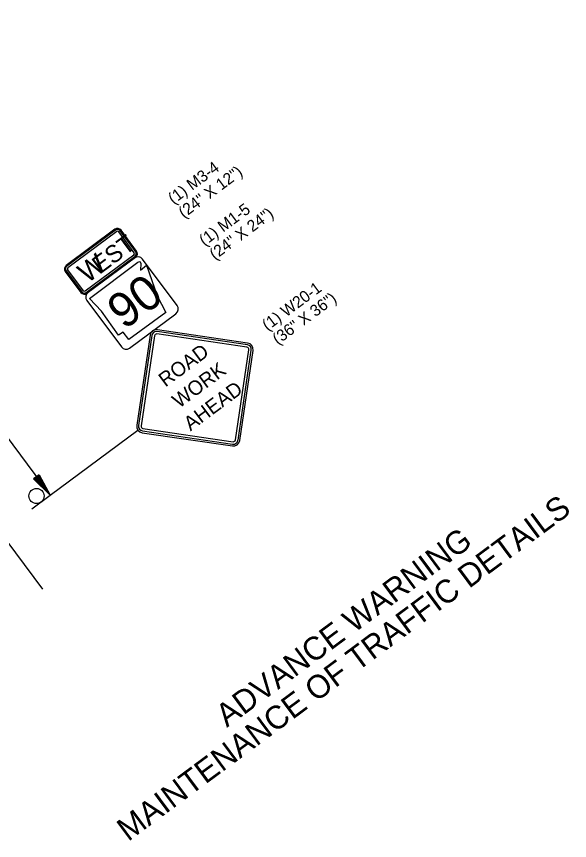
# Model space of a CAD drawing. Extents: x 998982 to 1000630, y 1875366 to 1876934.
# Drawn here: x 1000343 to 1000629.9, y 1875977.1 to 1876404.6 of the extents above; entities that cross this region are included whole.
import ezdxf

# ---------------------------------------------------------------- set-up
doc = ezdxf.new("R2010")
doc.units = 0
for name, color, linetype in [('P_TC_Signs_Permanent', 7, 'Continuous'), ('P_TC_Signs_Temporary', 7, 'Continuous'), ('R_Border Prem', 7, 'Continuous'), ('R_Draft', 7, 'Continuous'), ('STAMP', 7, 'Continuous')]:
    doc.layers.add(name, color=color, linetype=linetype)

msp = doc.modelspace()

# ---------------------------------------------------------------- linework, layer by layer
at = {"layer": 'P_TC_Signs_Permanent'}
for p, q in [((1000394.11, 1876294.21), (1000368.82, 1876275.43)), ((1000394.44, 1876293.76), (1000369.15, 1876274.98)), ((1000395, 1876293), (1000369.71, 1876274.23)), ((1000404.1, 1876282.01), (1000396.05, 1876292.85)), ((1000404.85, 1876282.57), (1000396.8, 1876293.41)), ((1000405.3, 1876282.91), (1000397.26, 1876293.74)), ((1000378.65, 1876262.18), (1000403.94, 1876280.96)), ((1000379.21, 1876261.43), (1000404.5, 1876280.21)), ((1000379.55, 1876260.98), (1000404.84, 1876279.76)), ((1000404.24, 1876279.31), (1000380.15, 1876261.43)), ((1000426.32, 1876254.6), (1000408.43, 1876278.69)), ((1000368.35, 1876272.28), (1000376.4, 1876261.44)), ((1000368.8, 1876272.62), (1000376.85, 1876261.78)), ((1000369.56, 1876273.18), (1000377.61, 1876262.34)), ((1000379.53, 1876257.23), (1000397.42, 1876233.14)), ((1000401.61, 1876232.52), (1000425.7, 1876250.41))]:
    msp.add_line(p, q, dxfattribs=at)
msp.add_lwpolyline([(1000406.76, 1876277.56), (1000407.25, 1876277.23), (1000407.6, 1876276.4), (1000407.39, 1876273.03), (1000410.54, 1876275.55), (1000415.92, 1876259.73), (1000420.57, 1876251.1), (1000401.38, 1876236.97), (1000398.39, 1876240.88), (1000395.88, 1876239.18), (1000387.17, 1876251.65), (1000380.86, 1876258.31), (1000405.98, 1876277.09), (1000406.76, 1876277.56)], dxfattribs=at)
for centre, radius, start, end in [((1000395.45, 1876292.4), 2.25, 36.5953, 126.5953), ((1000395.45, 1876292.4), 1.69, 36.5953, 126.5953), ((1000395.45, 1876292.4), 0.75, 36.5953, 126.5953), ((1000403.5, 1876281.56), 0.75, 306.5953, 36.5953), ((1000406.03, 1876276.9), 3, 36.5953, 126.5953), ((1000403.5, 1876281.56), 1.69, 306.5953, 36.5953), ((1000403.5, 1876281.56), 2.25, 306.5953, 36.5953), ((1000370.16, 1876273.62), 2.25, 126.5953, 216.5953), ((1000370.16, 1876273.62), 1.69, 126.5953, 216.5953), ((1000370.16, 1876273.62), 0.75, 126.5953, 216.5953), ((1000378.21, 1876262.79), 2.25, 216.5953, 306.5953), ((1000378.21, 1876262.79), 1.69, 216.5953, 306.5953), ((1000378.21, 1876262.79), 0.75, 216.5953, 306.5953), ((1000381.94, 1876259.02), 3, 126.5953, 216.5953), ((1000423.91, 1876252.82), 3, 306.5953, 36.5953), ((1000399.82, 1876234.93), 3, 216.5953, 306.5953)]:
    msp.add_arc(centre, radius, start, end, dxfattribs=at)
at = {"layer": 'P_TC_Signs_Temporary'}
for p, q in [((1000462.77, 1876234.26), (1000416.02, 1876241.17)), ((1000462.9, 1876235.19), (1000416.16, 1876242.09)), ((1000412.33, 1876239.25), (1000405.42, 1876192.51)), ((1000413.26, 1876239.11), (1000406.35, 1876192.37)), ((1000414.55, 1876238.92), (1000407.65, 1876192.18)), ((1000462.57, 1876232.96), (1000415.83, 1876239.87)), ((1000456.62, 1876184.94), (1000463.52, 1876231.68)), ((1000457.92, 1876184.75), (1000464.82, 1876231.49)), ((1000458.84, 1876184.61), (1000465.75, 1876231.36)), ((1000408.6, 1876190.9), (1000455.34, 1876183.99)), ((1000408.27, 1876188.67), (1000455.01, 1876181.77)), ((1000408.41, 1876189.6), (1000455.15, 1876182.7))]:
    msp.add_line(p, q, dxfattribs=at)
for centre, radius, start, end in [((1000415.67, 1876238.76), 3.38, 81.5953, 171.5953), ((1000415.67, 1876238.76), 2.44, 81.5953, 171.5953), ((1000415.67, 1876238.76), 1.13, 81.5953, 171.5953), ((1000462.41, 1876231.85), 1.12, 351.5953, 81.5953), ((1000462.41, 1876231.85), 2.44, 351.5953, 81.5953), ((1000462.41, 1876231.85), 3.38, 351.5953, 81.5953), ((1000408.76, 1876192.01), 3.38, 171.5953, 261.5953), ((1000408.76, 1876192.01), 2.44, 171.5953, 261.5953), ((1000408.76, 1876192.01), 1.12, 171.5953, 261.5953), ((1000455.5, 1876185.11), 3.38, 261.5953, 351.5953), ((1000455.5, 1876185.11), 2.44, 261.5953, 351.5953), ((1000455.5, 1876185.11), 1.13, 261.5953, 351.5953)]:
    msp.add_arc(centre, radius, start, end, dxfattribs=at)
at = {"layer": 'R_Draft'}
for p, q in [((1000356.62, 1876107.48), (1000045.75, 1876526.13)), ((1000241.26, 1876316.75), (1000360.5, 1876156.17)), ((1000360.5, 1876156.17), (1000406.05, 1876190)), ((1000354.8, 1876166.85), (1000351.92, 1876164.71)), ((1000351.92, 1876164.71), (1000360.5, 1876156.17)), ((1000352.16, 1876164.89), (1000359.3, 1876157.78)), ((1000352.4, 1876165.07), (1000358.08, 1876159.43)), ((1000352.64, 1876165.25), (1000356.89, 1876161.03)), ((1000352.89, 1876165.44), (1000355.68, 1876162.66)), ((1000353.14, 1876165.62), (1000354.49, 1876164.27)), ((1000353.59, 1876165.95), (1000354.49, 1876164.27)), ((1000353.83, 1876166.13), (1000355.68, 1876162.66)), ((1000354.08, 1876166.32), (1000356.89, 1876161.03)), ((1000354.32, 1876166.49), (1000358.08, 1876159.43)), ((1000354.56, 1876166.68), (1000359.3, 1876157.78)), ((1000354.8, 1876166.85), (1000360.5, 1876156.17))]:
    msp.add_line(p, q, dxfattribs=at)
at = {"layer": 'STAMP'}
msp.add_line((1000351.06, 1876149.17), (1000360.49, 1876156.18), dxfattribs=at)
msp.add_circle((1000353.44, 1876155.82), 3.92, dxfattribs=at)

# ---------------------------------------------------------------- texts
at = {"layer": 'P_TC_Signs_Permanent'}
for s, height, p in [('EST', 9, (1000386.5, 1876270.81)), ('W', 10.5, (1000379.85, 1876265.87)), ('90', 18, (1000398.9, 1876241.71))]:
    msp.add_text(s, height=height, rotation=36.5953, dxfattribs=at).set_placement(p)
at = {"layer": 'P_TC_Signs_Temporary'}
for s, p in [(' ROAD ', (1000418.03, 1876210.37)), ('WORK', (1000427.36, 1876201.08)), ('AHEAD', (1000433.29, 1876189.26))]:
    msp.add_text(s, height=7.5, rotation=36.5953, dxfattribs=at).set_placement(p)
at = {"layer": 'R_Border Prem'}
for s, height, p in [('(1) M3-4', 6, (1000424.43, 1876306.94)), ('(24" X 12")', 6, (1000429.8, 1876299.71)), ('(1) M1-5', 6, (1000440.53, 1876285.26)), ('(24" X 24")', 6, (1000445.9, 1876278.03)), ('(1) W20-1', 6, (1000473.19, 1876241.27)), ('(36" X 36")', 6, (1000478.56, 1876234.05)), ('MAINTENANCE OF TRAFFIC DETAILS', 12, (1000400.94, 1875976.28)), ('ADVANCE WARNING ', 12, (1000452.14, 1876035.48))]:
    msp.add_text(s, height=height, rotation=36.5953, dxfattribs=at).set_placement(p)

doc.saveas('drawing.dxf')
